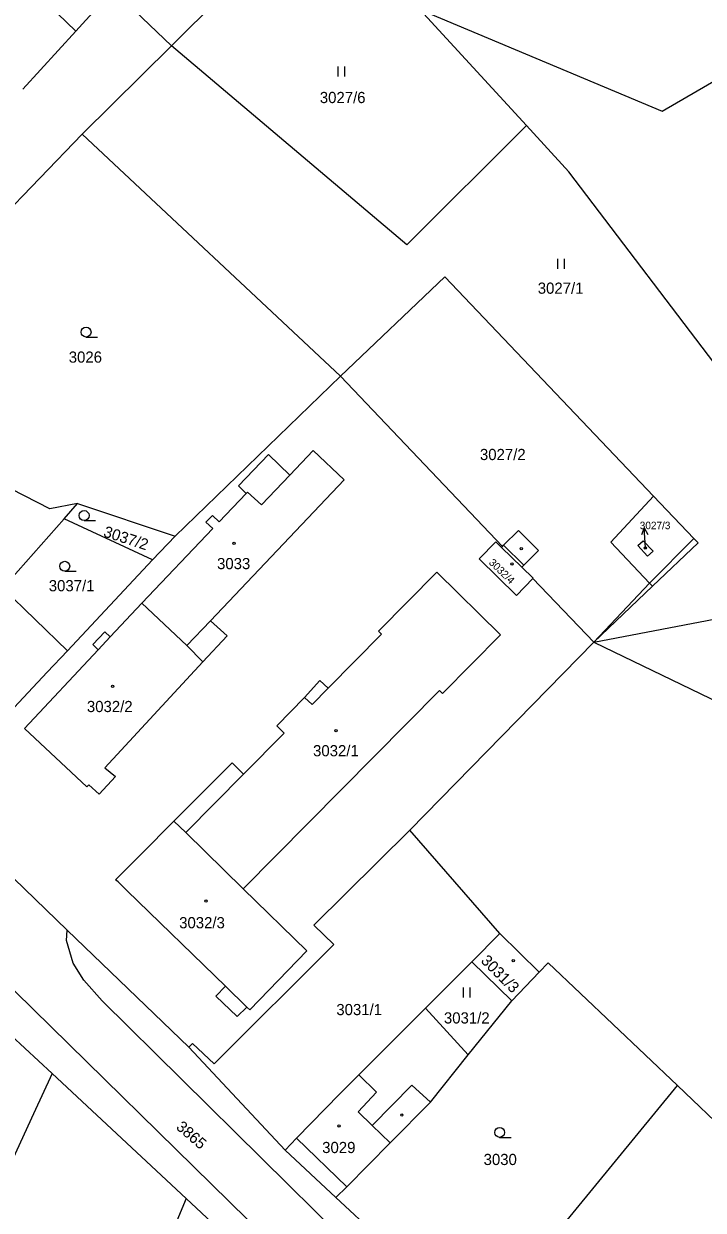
# Model space of a CAD drawing. Extents: x -527335 to -526256, y -1079142 to -1077836.
# Drawn here: x -526577.1 to -526473.7, y -1078894.6 to -1078714.2 of the extents above; entities that cross this region are included whole.
import ezdxf

# ---------------------------------------------------------------- set-up
doc = ezdxf.new("R2010")
doc.units = 0
for name, color, linetype in [('Hranice parcel', 7, 'Continuous'), ('Parcelní čísla', 7, 'Continuous'), ('Pop  PČ popisy', 7, 'Continuous'), ('Vnitřní kresba', 7, 'Continuous'), ('Značky budov', 7, 'Continuous'), ('Značky kultur', 7, 'Continuous')]:
    doc.layers.add(name, color=color, linetype=linetype)

msp = doc.modelspace()

# ---------------------------------------------------------------- linework, layer by layer
at = {"layer": 'Hranice parcel'}
for p, q in [((-526554.68, -1078717.53), (-526539.54, -1078702.51)), ((-526516.89, -1078712.01), (-526500.66, -1078729.66)), ((-526577.27, -1078724.14), (-526569.24, -1078715.32)), ((-526568.24, -1078730.99), (-526554.68, -1078717.53)), ((-526602.93, -1078766.96), (-526568.24, -1078730.99)), ((-526528.93, -1078767.79), (-526568.24, -1078730.99)), ((-526554.11, -1078792.09), (-526528.93, -1078767.79)), ((-526528.93, -1078767.79), (-526504.29, -1078793.67)), ((-526571, -1078789.45), (-526568.95, -1078787.13)), ((-526568.95, -1078787.13), (-526554.11, -1078792.09)), ((-526580.33, -1078800.02), (-526571, -1078789.45)), ((-526557.53, -1078795.73), (-526571, -1078789.45)), ((-526554.11, -1078792.09), (-526557.53, -1078795.73)), ((-526570.48, -1078809.52), (-526557.53, -1078795.73)), ((-526499.66, -1078798.54), (-526490.41, -1078808.25)), ((-526570.48, -1078809.52), (-526580.33, -1078800.02)), ((-526481.45, -1078799.72), (-526490.41, -1078808.25)), ((-526490.41, -1078808.25), (-526446.22, -1078799.76)), ((-526573.56, -1078812.8), (-526570.48, -1078809.52)), ((-526518.39, -1078836.79), (-526490.41, -1078808.25)), ((-526490.41, -1078808.25), (-526410.53, -1078846.68)), ((-526504.69, -1078852.51), (-526518.39, -1078836.79)), ((-526572.83, -1078873.83), (-526599.63, -1078848.92)), ((-526508.94, -1078856.81), (-526504.69, -1078852.51)), ((-526504.69, -1078852.51), (-526498.72, -1078858.41)), ((-526508.94, -1078856.81), (-526516.02, -1078863.88)), ((-526502.9, -1078862.78), (-526508.94, -1078856.81)), ((-526498.72, -1078858.41), (-526502.9, -1078862.78)), ((-526509.51, -1078870.99), (-526502.9, -1078862.78)), ((-526516.02, -1078863.88), (-526526.14, -1078873.99)), ((-526509.51, -1078870.99), (-526516.02, -1078863.88)), ((-526552.02, -1078869.8), (-526537.38, -1078885.46)), ((-526515.27, -1078878.15), (-526509.51, -1078870.99)), ((-526552.41, -1078892.82), (-526572.83, -1078873.83)), ((-526508.07, -1078912.73), (-526477.68, -1078875.63)), ((-526477.68, -1078875.63), (-526463.23, -1078889.43)), ((-526537.38, -1078885.46), (-526529.63, -1078892.67)), ((-526552.41, -1078892.82), (-526555.43, -1078899.96)), ((-526534.91, -1078909.1), (-526552.41, -1078892.82)), ((-526529.63, -1078892.67), (-526508.07, -1078912.73))]:
    msp.add_line(p, q, dxfattribs=at)
for points in [[(-526569.24, -1078715.32), (-526590.17, -1078695.14), (-526598.14, -1078704.26)], [(-526554.68, -1078717.53), (-526563.51, -1078709.03), (-526569.24, -1078715.32)], [(-526516.89, -1078712.01), (-526480.01, -1078727.48), (-526459.29, -1078715.49)], [(-526500.66, -1078729.66), (-526518.84, -1078747.8), (-526554.68, -1078717.53)], [(-526446.22, -1078799.76), (-526494.18, -1078736.71), (-526500.66, -1078729.66)], [(-526528.93, -1078767.79), (-526513.06, -1078752.68), (-526481.31, -1078786.03)], [(-526559.18, -1078802.32), (-526548.37, -1078790.96), (-526549.41, -1078789.97), (-526548.43, -1078788.98), (-526547.41, -1078789.95), (-526543.29, -1078785.62), (-526544.48, -1078784.47), (-526539.92, -1078779.69), (-526536.66, -1078782.81), (-526533.1, -1078779.08), (-526528.38, -1078783.55), (-526548.71, -1078804.96)], [(-526568.95, -1078787.13), (-526573.17, -1078787.97), (-526583, -1078782.94)], [(-526481.45, -1078799.72), (-526481.91, -1078799.24), (-526487.82, -1078793.01), (-526481.31, -1078786.03)], [(-526481.31, -1078786.03), (-526475.18, -1078792.47), (-526474.54, -1078793.14), (-526481.45, -1078799.72)], [(-526504.29, -1078793.67), (-526504.13, -1078793.49), (-526501.86, -1078791.24), (-526498.83, -1078794.3), (-526501.07, -1078796.51), (-526501.37, -1078796.8), (-526499.64, -1078798.52), (-526499.66, -1078798.54)], [(-526499.66, -1078798.54), (-526502.17, -1078801.11), (-526507.83, -1078795.56), (-526505.29, -1078792.97), (-526504.44, -1078793.81), (-526504.29, -1078793.67)], [(-526548.71, -1078804.96), (-526546.18, -1078807.27), (-526549.87, -1078811.21), (-526564.78, -1078827.33), (-526563.18, -1078828.67), (-526565.67, -1078831.32), (-526567.24, -1078829.94), (-526567.55, -1078830.24), (-526577.02, -1078821.35), (-526565.81, -1078809.39), (-526566.65, -1078808.6), (-526564.81, -1078806.64), (-526563.97, -1078807.43), (-526559.18, -1078802.32)], [(-526548.71, -1078804.96), (-526552.31, -1078808.75), (-526559.18, -1078802.32)], [(-526592.15, -1078831.2), (-526590.73, -1078829.68), (-526583.18, -1078822.03), (-526580.48, -1078819.73), (-526580.05, -1078819.71), (-526573.56, -1078812.8)], [(-526592.15, -1078831.2), (-526581.94, -1078841.02), (-526570.51, -1078852.02), (-526552.02, -1078869.8)], [(-526534.07, -1078855.15), (-526542.75, -1078864.11), (-526543.21, -1078863.71), (-526544.66, -1078865.16), (-526547.92, -1078862.03), (-526546.45, -1078860.51), (-526561.4, -1078846.03), (-526562.78, -1078844.67), (-526563.17, -1078844.34), (-526559.27, -1078840.44), (-526554.28, -1078835.46), (-526552.5, -1078837.19), (-526543.73, -1078845.74), (-526534.07, -1078855.15)], [(-526518.39, -1078836.79), (-526533.02, -1078851.25), (-526529.98, -1078854.21), (-526548.16, -1078872.34), (-526551.44, -1078869.24), (-526552.02, -1078869.8)], [(-526477.68, -1078875.63), (-526497.36, -1078856.99), (-526498.72, -1078858.41)], [(-526572.83, -1078873.83), (-526575.65, -1078879.95), (-526588.32, -1078907.48)], [(-526526.14, -1078873.99), (-526529.07, -1078876.91), (-526535.65, -1078883.66), (-526537.38, -1078885.46)], [(-526529.63, -1078892.67), (-526527.96, -1078891.05), (-526521.37, -1078884.35), (-526515.27, -1078878.15)]]:
    msp.add_lwpolyline(points, dxfattribs=at)
at = {"layer": 'Pop  PČ popisy'}
for p, q in [((-526482.72, -1078790.86), (-526483.17, -1078791.89)), ((-526482.56, -1078793.86), (-526482.72, -1078790.86)), ((-526482.72, -1078790.86), (-526482.17, -1078791.84)), ((-526482.56, -1078793.92), (-526482.56, -1078793.86))]:
    msp.add_line(p, q, dxfattribs=at)
at = {"layer": 'Vnitřní kresba'}
for p, q in [((-526536.66, -1078782.81), (-526540.99, -1078787.35)), ((-526543.09, -1078785.41), (-526543.29, -1078785.62)), ((-526540.99, -1078787.35), (-526543.09, -1078785.41)), ((-526483.68, -1078793.55), (-526482.89, -1078792.8)), ((-526482.89, -1078792.8), (-526481.39, -1078794.38)), ((-526481.91, -1078799.24), (-526475.18, -1078792.47)), ((-526504.44, -1078793.81), (-526501.37, -1078796.8)), ((-526504.13, -1078793.49), (-526501.07, -1078796.51)), ((-526482.21, -1078795.15), (-526483.68, -1078793.55)), ((-526481.39, -1078794.38), (-526482.21, -1078795.15)), ((-526514.27, -1078797.58), (-526523.14, -1078806.56)), ((-526504.59, -1078807.11), (-526514.27, -1078797.58)), ((-526490.41, -1078808.25), (-526481.91, -1078799.24)), ((-526565.81, -1078809.39), (-526563.97, -1078807.43)), ((-526522.69, -1078807.01), (-526530.82, -1078815.24)), ((-526523.14, -1078806.56), (-526522.69, -1078807.01)), ((-526513.43, -1078816.03), (-526504.59, -1078807.11)), ((-526552.31, -1078808.75), (-526549.87, -1078811.21)), ((-526532.07, -1078814.05), (-526534.4, -1078816.62)), ((-526530.82, -1078815.24), (-526532.07, -1078814.05)), ((-526543.73, -1078845.74), (-526513.87, -1078815.59)), ((-526534.4, -1078816.62), (-526538.64, -1078820.95)), ((-526534.4, -1078816.62), (-526533.28, -1078817.73)), ((-526533.28, -1078817.73), (-526530.82, -1078815.24)), ((-526513.87, -1078815.59), (-526513.43, -1078816.03)), ((-526537.54, -1078822.04), (-526543.7, -1078828.28)), ((-526538.64, -1078820.95), (-526537.54, -1078822.04)), ((-526545.43, -1078826.57), (-526554.28, -1078835.46)), ((-526543.7, -1078828.28), (-526545.43, -1078826.57)), ((-526552.5, -1078837.19), (-526543.7, -1078828.28)), ((-526483.62, -1078954.28), (-526598.1, -1078842.1)), ((-526570.66, -1078853.6), (-526570.51, -1078852.02)), ((-526569.64, -1078857.03), (-526570.66, -1078853.6)), ((-526568.01, -1078859.64), (-526569.64, -1078857.03)), ((-526565.2, -1078862.78), (-526568.01, -1078859.64)), ((-526543.21, -1078863.71), (-526546.45, -1078860.51)), ((-526481.85, -1078944.96), (-526565.2, -1078862.78)), ((-526526.14, -1078873.99), (-526523.47, -1078876.63)), ((-526524.13, -1078881.72), (-526518.08, -1078875.58)), ((-526518.08, -1078875.58), (-526515.27, -1078878.15)), ((-526523.47, -1078876.63), (-526526.25, -1078879.65)), ((-526526.25, -1078879.65), (-526524.13, -1078881.72)), ((-526524.13, -1078881.72), (-526521.37, -1078884.35)), ((-526535.65, -1078883.66), (-526527.96, -1078891.05))]:
    msp.add_line(p, q, dxfattribs=at)
at = {"layer": 'Značky budov'}
for centre in [(-526545.14, -1078793.18), (-526501.44, -1078794), (-526482.57, -1078793.89), (-526502.87, -1078796.33), (-526563.63, -1078814.95), (-526529.62, -1078821.67), (-526549.42, -1078847.6), (-526502.65, -1078856.67), (-526519.61, -1078880.14), (-526529.16, -1078881.78)]:
    msp.add_circle(centre, 0.175, dxfattribs=at)
at = {"layer": 'Značky kultur'}
for p, q in [((-526529.3, -1078722.22), (-526529.3, -1078720.72)), ((-526528.3, -1078722.22), (-526528.3, -1078720.72)), ((-526495.88, -1078751.45), (-526495.88, -1078749.95)), ((-526494.88, -1078751.45), (-526494.88, -1078749.95)), ((-526567.65, -1078761.83), (-526565.9, -1078761.83)), ((-526567.95, -1078789.72), (-526566.2, -1078789.72)), ((-526570.9, -1078797.43), (-526569.15, -1078797.43)), ((-526510.22, -1078862.25), (-526510.22, -1078860.75)), ((-526509.22, -1078862.25), (-526509.22, -1078860.75)), ((-526504.73, -1078883.52), (-526502.98, -1078883.52))]:
    msp.add_line(p, q, dxfattribs=at)
for centre in [(-526567.65, -1078761.08), (-526567.95, -1078788.97), (-526570.9, -1078796.68), (-526504.73, -1078882.77)]:
    msp.add_circle(centre, 0.75, dxfattribs=at)

# ---------------------------------------------------------------- texts
at = {"layer": 'Parcelní čísla'}
for s, height, p in [('3027/6', 1.7, (-526532.09, -1078726.26)), ('3027/1', 1.7, (-526498.93, -1078755.25)), ('3026', 1.7, (-526570.29, -1078765.73)), ('3027/2', 1.7, (-526507.73, -1078780.54)), ('3027/3', 1.139, (-526483.41, -1078791.05)), ('3033', 1.7, (-526547.73, -1078797.13)), ('3037/1', 1.7, (-526573.33, -1078800.49)), ('3032/2', 1.7, (-526567.53, -1078818.86)), ('3032/1', 1.7, (-526533.12, -1078825.58)), ('3032/3', 1.7, (-526553.49, -1078851.73)), ('3031/1', 1.7, (-526529.58, -1078864.94)), ('3031/2', 1.7, (-526513.21, -1078866.21)), ('3029', 1.7, (-526531.73, -1078885.91)), ('3030', 1.7, (-526507.17, -1078887.73))]:
    msp.add_text(s, height=height, dxfattribs=at).set_placement(p)
for s, height, rotation, p in [('3037/2', 1.7, 342, (-526565.13, -1078792.13)), ('3032/4', 1.14, 316, (-526506.46, -1078796.24)), ('3031/3', 1.7, 315, (-526507.7, -1078856.79)), ('3865', 1.7, 319, (-526554.08, -1078882.14))]:
    msp.add_text(s, height=height, rotation=rotation, dxfattribs=at).set_placement(p)

doc.saveas('drawing.dxf')
